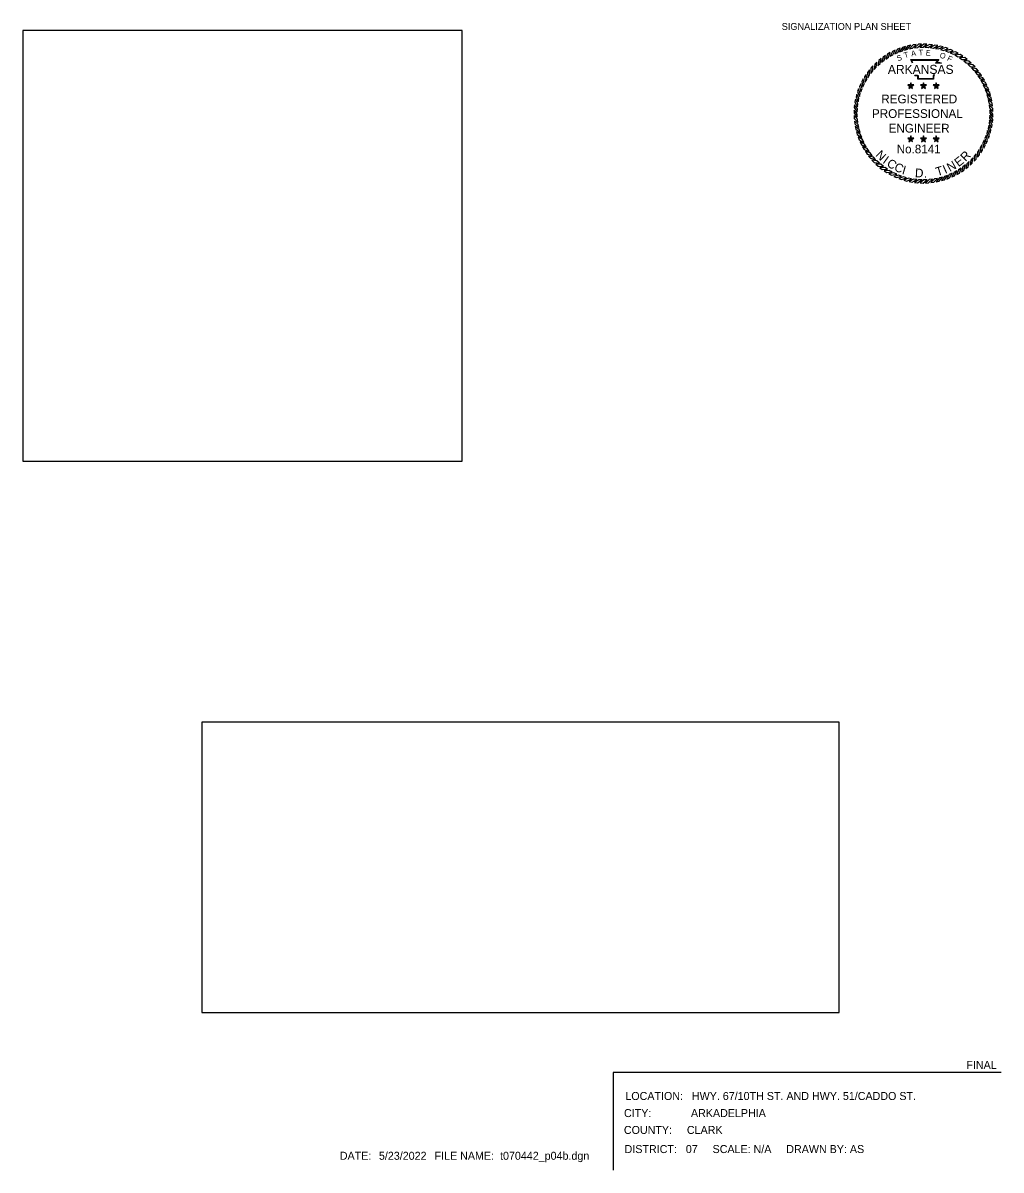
# Model space of a CAD drawing. Extents: x 418532 to 419834, y -565899 to -565283.
# Drawn here: x 419321 to 419834, y -565899 to -565297 of the extents above; entities that cross this region are included whole.
import ezdxf

# ---------------------------------------------------------------- set-up
doc = ezdxf.new("R2010")
doc.units = 0
for name, color, linetype in [('G-ANNO-SYMB', 7, 'Continuous'), ('G-ANNO-TEXT', 7, 'Continuous'), ('Level 10', 7, 'Continuous'), ('Level 57', 7, 'Continuous'), ('V-SIGNAL-LOOP', 7, 'Continuous')]:
    doc.layers.add(name, color=color, linetype=linetype)

msp = doc.modelspace()

# ---------------------------------------------------------------- linework, layer by layer
at = {"layer": 'G-ANNO-SYMB'}
for points in [[(419773.51, -565313.59), (419772.22, -565314.48), (419771.45, -565317.17), (419772.79, -565316.13)], [(419775.97, -565312.12), (419774.61, -565312.9), (419773.63, -565315.52), (419775.05, -565314.59)], [(419778.54, -565310.85), (419777.12, -565311.52), (419775.94, -565314.06), (419777.42, -565313.24)], [(419781.19, -565309.78), (419779.73, -565310.34), (419778.35, -565312.77), (419779.9, -565312.08)], [(419783.93, -565308.93), (419782.42, -565309.37), (419780.86, -565311.69), (419782.45, -565311.11)], [(419786.72, -565308.29), (419785.18, -565308.61), (419783.44, -565310.8), (419785.08, -565310.35)], [(419789.55, -565307.87), (419788, -565308.07), (419786.09, -565310.12), (419787.75, -565309.8)], [(419792.41, -565307.68), (419790.84, -565307.75), (419788.78, -565309.64), (419790.47, -565309.46)], [(419795.27, -565307.71), (419793.71, -565307.66), (419791.5, -565309.38), (419793.2, -565309.33)], [(419798.13, -565307.96), (419796.57, -565307.79), (419794.23, -565309.34), (419795.93, -565309.42)], [(419800.95, -565308.44), (419799.41, -565308.15), (419796.96, -565309.51), (419798.64, -565309.72)], [(419803.73, -565309.14), (419802.21, -565308.73), (419799.67, -565309.89), (419801.33, -565310.23)], [(419806.44, -565310.05), (419804.96, -565309.52), (419802.34, -565310.48), (419803.96, -565310.95)], [(419809.08, -565311.18), (419807.64, -565310.53), (419804.95, -565311.28), (419806.54, -565311.88)], [(419811.61, -565312.5), (419810.24, -565311.75), (419807.49, -565312.29), (419809.03, -565313.01)], [(419814.04, -565314.03), (419812.73, -565313.17), (419809.95, -565313.48), (419811.42, -565314.32)], [(419766.93, -565319.09), (419765.88, -565320.25), (419765.76, -565323.05), (419766.82, -565321.72)], [(419768.98, -565317.09), (419767.84, -565318.16), (419767.5, -565320.94), (419768.66, -565319.7)], [(419771.18, -565315.25), (419769.96, -565316.24), (419769.4, -565318.98), (419770.65, -565317.83)], [(419816.34, -565315.73), (419815.1, -565314.78), (419812.3, -565314.87), (419813.7, -565315.83)], [(419818.5, -565317.62), (419817.33, -565316.56), (419814.54, -565316.44), (419815.86, -565317.5)], [(419820.5, -565319.66), (419819.42, -565318.52), (419816.65, -565318.18), (419817.88, -565319.34)], [(419763.34, -565323.55), (419762.48, -565324.86), (419762.8, -565327.64), (419763.64, -565326.17)], [(419765.05, -565321.25), (419764.09, -565322.49), (419764.19, -565325.29), (419765.14, -565323.88)], [(419822.34, -565321.86), (419821.35, -565320.64), (419818.61, -565320.08), (419819.75, -565321.34)], [(419823.99, -565324.2), (419823.11, -565322.9), (419820.42, -565322.13), (419821.46, -565323.47)], [(419825.46, -565326.65), (419824.68, -565325.29), (419822.06, -565324.31), (419823, -565325.73)], [(419759.37, -565331.15), (419758.84, -565332.62), (419759.8, -565335.25), (419760.27, -565333.62)], [(419760.49, -565328.51), (419759.85, -565329.94), (419760.6, -565332.64), (419761.2, -565331.05)], [(419761.82, -565325.97), (419761.07, -565327.35), (419761.6, -565330.09), (419762.32, -565328.56)], [(419786.78, -565329.61), (419786.41, -565329.1), (419785.2, -565329.1), (419786.18, -565329.81)], [(419786.78, -565329.61), (419786.18, -565329.81), (419785.8, -565330.96), (419786.78, -565330.25)], [(419786.78, -565329.61), (419787.16, -565329.1), (419786.78, -565327.94), (419786.41, -565329.1)], [(419786.78, -565329.61), (419787.39, -565329.81), (419788.37, -565329.1), (419787.16, -565329.1)], [(419786.78, -565329.61), (419786.78, -565330.25), (419787.76, -565330.96), (419787.39, -565329.81)], [(419793.45, -565329.61), (419793.08, -565329.1), (419791.87, -565329.1), (419792.85, -565329.81)], [(419793.45, -565329.61), (419792.85, -565329.81), (419792.47, -565330.96), (419793.45, -565330.25)], [(419793.45, -565329.61), (419793.83, -565329.1), (419793.45, -565327.94), (419793.08, -565329.1)], [(419793.45, -565329.61), (419794.06, -565329.81), (419795.04, -565329.1), (419793.83, -565329.1)], [(419793.45, -565329.61), (419793.45, -565330.25), (419794.43, -565330.96), (419794.06, -565329.81)], [(419800.12, -565329.61), (419799.75, -565329.1), (419798.54, -565329.1), (419799.52, -565329.81)], [(419800.12, -565329.61), (419799.52, -565329.81), (419799.14, -565330.96), (419800.12, -565330.25)], [(419800.12, -565329.61), (419800.5, -565329.1), (419800.12, -565327.94), (419799.75, -565329.1)], [(419800.12, -565329.61), (419800.73, -565329.81), (419801.71, -565329.1), (419800.5, -565329.1)], [(419800.12, -565329.61), (419800.12, -565330.25), (419801.1, -565330.96), (419800.73, -565329.81)], [(419826.74, -565329.22), (419826.07, -565327.8), (419823.53, -565326.62), (419824.35, -565328.11)], [(419827.81, -565331.88), (419827.25, -565330.41), (419824.81, -565329.03), (419825.51, -565330.58)], [(419828.66, -565334.61), (419828.22, -565333.11), (419825.9, -565331.54), (419826.48, -565333.14)], [(419757.76, -565336.64), (419757.47, -565338.18), (419758.82, -565340.62), (419759.03, -565338.94)], [(419758.45, -565333.86), (419758.04, -565335.37), (419759.2, -565337.92), (419759.55, -565336.26)], [(419829.3, -565337.4), (419828.98, -565335.87), (419826.79, -565334.13), (419827.24, -565335.76)], [(419829.72, -565340.24), (419829.52, -565338.68), (419827.47, -565336.77), (419827.79, -565338.44)], [(419757.02, -565342.31), (419756.98, -565343.88), (419758.7, -565346.08), (419758.64, -565344.39)], [(419757.28, -565339.46), (419757.11, -565341.02), (419758.65, -565343.35), (419758.73, -565341.66)], [(419829.91, -565343.09), (419829.83, -565341.53), (419827.94, -565339.47), (419828.13, -565341.15)], [(419829.88, -565345.96), (419829.93, -565344.39), (419828.2, -565342.19), (419828.26, -565343.88)], [(419756.99, -565345.18), (419757.07, -565346.74), (419758.96, -565348.81), (419758.77, -565347.12)], [(419757.19, -565348.04), (419757.39, -565349.59), (419759.43, -565351.5), (419759.11, -565349.83)], [(419829.15, -565351.63), (419829.44, -565350.09), (419828.08, -565347.65), (419827.87, -565349.33)], [(419829.63, -565348.81), (419829.79, -565347.25), (419828.25, -565344.92), (419828.17, -565346.61)], [(419757.6, -565350.87), (419757.93, -565352.4), (419760.11, -565354.14), (419759.67, -565352.51)], [(419758.24, -565353.66), (419758.68, -565355.17), (419761, -565356.73), (419760.43, -565355.13)], [(419826.41, -565359.76), (419827.05, -565358.33), (419826.31, -565355.63), (419825.71, -565357.22)], [(419827.54, -565357.13), (419828.06, -565355.65), (419827.11, -565353.02), (419826.63, -565354.65)], [(419828.45, -565354.41), (419828.86, -565352.9), (419827.7, -565350.35), (419827.36, -565352.01)], [(419759.1, -565356.39), (419759.66, -565357.86), (419762.09, -565359.24), (419761.39, -565357.69)], [(419760.17, -565359.05), (419760.84, -565360.47), (419763.37, -565361.65), (419762.55, -565360.17)], [(419761.44, -565361.62), (419762.22, -565362.98), (419764.84, -565363.96), (419763.91, -565362.54)], [(419786.78, -565357.54), (419786.41, -565357.03), (419785.2, -565357.03), (419786.18, -565357.74)], [(419786.78, -565357.54), (419786.18, -565357.74), (419785.8, -565358.89), (419786.78, -565358.18)], [(419786.78, -565357.54), (419787.16, -565357.03), (419786.78, -565355.87), (419786.41, -565357.03)], [(419786.78, -565357.54), (419787.39, -565357.74), (419788.37, -565357.03), (419787.16, -565357.03)], [(419786.78, -565357.54), (419786.78, -565358.18), (419787.76, -565358.89), (419787.39, -565357.74)], [(419793.45, -565357.54), (419793.08, -565357.03), (419791.87, -565357.03), (419792.85, -565357.74)], [(419793.45, -565357.54), (419792.85, -565357.74), (419792.47, -565358.89), (419793.45, -565358.18)], [(419793.45, -565357.54), (419793.83, -565357.03), (419793.45, -565355.87), (419793.08, -565357.03)], [(419793.45, -565357.54), (419794.06, -565357.74), (419795.04, -565357.03), (419793.83, -565357.03)], [(419793.45, -565357.54), (419793.45, -565358.18), (419794.43, -565358.89), (419794.06, -565357.74)], [(419800.12, -565357.54), (419799.75, -565357.03), (419798.54, -565357.03), (419799.52, -565357.74)], [(419800.12, -565357.54), (419799.52, -565357.74), (419799.14, -565358.89), (419800.12, -565358.18)], [(419800.12, -565357.54), (419800.5, -565357.03), (419800.12, -565355.87), (419799.75, -565357.03)], [(419800.12, -565357.54), (419800.73, -565357.74), (419801.71, -565357.03), (419800.5, -565357.03)], [(419800.12, -565357.54), (419800.12, -565358.18), (419801.1, -565358.89), (419800.73, -565357.74)], [(419823.56, -565364.72), (419824.42, -565363.41), (419824.1, -565360.63), (419823.26, -565362.1)], [(419825.08, -565362.3), (419825.84, -565360.92), (419825.3, -565358.18), (419824.58, -565359.71)], [(419762.91, -565364.07), (419763.79, -565365.37), (419766.48, -565366.14), (419765.44, -565364.8)], [(419764.57, -565366.41), (419765.55, -565367.63), (419768.29, -565368.19), (419767.15, -565366.94)], [(419817.92, -565371.18), (419819.06, -565370.11), (419819.4, -565367.33), (419818.24, -565368.57)], [(419819.97, -565369.18), (419821.02, -565368.02), (419821.14, -565365.22), (419820.09, -565366.55)], [(419821.85, -565367.02), (419822.81, -565365.78), (419822.71, -565362.99), (419821.76, -565364.39)], [(419766.4, -565368.61), (419767.48, -565369.75), (419770.26, -565370.09), (419769.02, -565368.93)], [(419768.41, -565370.65), (419769.57, -565371.71), (419772.36, -565371.83), (419771.04, -565370.77)], [(419770.57, -565372.54), (419771.81, -565373.49), (419774.6, -565373.4), (419773.2, -565372.45)], [(419810.93, -565376.15), (419812.29, -565375.37), (419813.27, -565372.75), (419811.86, -565373.68)], [(419813.39, -565374.68), (419814.69, -565373.79), (419815.46, -565371.11), (419814.12, -565372.14)], [(419815.73, -565373.02), (419816.95, -565372.04), (419817.5, -565369.3), (419816.25, -565370.44)], [(419772.86, -565374.25), (419774.18, -565375.1), (419776.96, -565374.79), (419775.48, -565373.95)], [(419775.29, -565375.77), (419776.67, -565376.52), (419779.41, -565375.99), (419777.88, -565375.26)], [(419777.83, -565377.1), (419779.26, -565377.74), (419781.95, -565376.99), (419780.37, -565376.39)], [(419780.46, -565378.22), (419781.94, -565378.75), (419784.57, -565377.79), (419782.94, -565377.32)], [(419783.18, -565379.13), (419784.69, -565379.54), (419787.23, -565378.38), (419785.57, -565378.04)], [(419785.95, -565379.83), (419787.5, -565380.12), (419789.94, -565378.77), (419788.26, -565378.55)], [(419788.78, -565380.31), (419790.34, -565380.48), (419792.67, -565378.93), (419790.98, -565378.86)], [(419791.63, -565380.57), (419793.2, -565380.61), (419795.4, -565378.89), (419793.71, -565378.94)], [(419794.49, -565380.6), (419796.06, -565380.52), (419798.12, -565378.63), (419796.44, -565378.81)], [(419797.35, -565380.4), (419798.91, -565380.2), (419800.81, -565378.16), (419799.15, -565378.47)], [(419800.18, -565379.98), (419801.72, -565379.66), (419803.46, -565377.47), (419801.83, -565377.92)], [(419802.98, -565379.34), (419804.48, -565378.9), (419806.05, -565376.59), (419804.45, -565377.16)], [(419805.71, -565378.49), (419807.18, -565377.93), (419808.55, -565375.5), (419807.01, -565376.19)], [(419808.37, -565377.42), (419809.78, -565376.75), (419810.97, -565374.22), (419809.48, -565375.03)]]:
    msp.add_lwpolyline(points, close=True, dxfattribs=at)
for points in [[(419787.61, -565317.66), (419786.76, -565315.82), (419801.47, -565315.81), (419800.24, -565317.36), (419801.24, -565317.34), (419802.08, -565317.33), (419802.91, -565317.42)], [(419787.82, -565317.56), (419787.12, -565316.05), (419800.99, -565316.05), (419799.75, -565317.6), (419801.24, -565317.58), (419802.06, -565317.57), (419802.88, -565317.66)], [(419799.15, -565323.83), (419798.9, -565324.03), (419798.82, -565324.34), (419798.73, -565325.1), (419798.73, -565326.12), (419790.52, -565326.12), (419790.52, -565324.74), (419790.52, -565324.44), (419790.19, -565324.34), (419789.02, -565324.34), (419788.81, -565324.02)], [(419799, -565323.65), (419798.7, -565323.9), (419798.59, -565324.29), (419798.5, -565325.09), (419798.5, -565325.88), (419790.75, -565325.88), (419790.75, -565324.74), (419790.75, -565324.27), (419790.22, -565324.1), (419789.15, -565324.1), (419789.01, -565323.89)]]:
    msp.add_lwpolyline(points, dxfattribs=at)
at = {"layer": 'Level 57'}
for points in [[(419630.59, -565847.55), (419630.59, -565898.75)], [(419834.17, -565847.55), (419630.59, -565847.55)]]:
    msp.add_lwpolyline(points, dxfattribs=at)
at = {"layer": 'V-SIGNAL-LOOP'}
for points in [[(419320.6, -565526.59), (419551.15, -565526.59), (419551.15, -565300.56), (419320.6, -565300.56)], [(419414.49, -565816.08), (419749.21, -565816.08), (419749.21, -565663.65), (419414.49, -565663.65)]]:
    msp.add_lwpolyline(points, close=True, dxfattribs=at)

# ---------------------------------------------------------------- texts
at = {"layer": 'G-ANNO-SYMB'}
for s, height, rotation, p in [('S', 2.9, 19.77256, (419779.95, -565316.7)), ('T', 2.9, 16.90148, (419783.64, -565315.04)), ('A', 2.9, 8.67877, (419787.16, -565314.12)), ('T', 2.9, 1.47887, (419790.91, -565313.54)), ('E', 2.9, 356.67203, (419794.62, -565313.63)), ('O', 2.9, 341.2218, (419801.67, -565314.63)), ('F', 2.9, 335.36282, (419805.58, -565316.16)), ('N', 4.59, 315.26758, (419767.97, -565366.13)), ('I', 4.59, 324.21406, (419771.7, -565369.83)), ('E', 4.59, 37.64979, (419811.88, -565372.31)), ('R', 4.59, 45.47796, (419815.54, -565369.54)), ('C', 4.59, 328.68731, (419773.77, -565371.45)), ('C', 4.59, 336.51548, (419777.67, -565373.87)), ('I', 4.59, 344.34365, (419781.87, -565375.74)), ('D', 4.59, 356.64507, (419788.87, -565377.49)), ('T', 4.59, 16.77466, (419800.63, -565377.03)), ('I', 4.59, 24.23006, (419804.84, -565375.82)), ('N', 4.59, 28.7033, (419807.27, -565374.83)), ('.', 4.59, 4.84601, (419793.68, -565377.8))]:
    msp.add_text(s, height=height, rotation=rotation, dxfattribs=at).set_placement(p)
for s, height, p in [('ARKANSAS', 4.737, (419774.73, -565323.3)), ('REGISTERED', 4.585, (419771.29, -565338.76)), ('PROFESSIONAL', 4.5855, (419766.38, -565346.43)), ('ENGINEER', 4.585, (419775.11, -565354.1)), ('No.8141', 4.567, (419779.38, -565365.03))]:
    msp.add_text(s, height=height, dxfattribs=at).set_placement(p)
at = {"layer": 'G-ANNO-TEXT'}
msp.add_text('SIGNALIZATION PLAN SHEET', height=3.6, dxfattribs=at).set_placement((419718.99, -565300.21))
at = {"layer": 'Level 10'}
for s, p in [('FINAL', (419815.96, -565845.65)), ('LOCATION:   HWY. 67/10TH ST. AND HWY. 51/CADDO ST.', (419636.9, -565861.97)), ('CITY:', (419636.19, -565870.93)), (' ARKADELPHIA', (419669.79, -565870.93)), ('COUNTY:     CLARK', (419636.14, -565879.8)), ('DISTRICT:   07     SCALE: N/A     DRAWN BY: AS', (419636.51, -565889.83)), ('DATE:  ', (419486.98, -565893.35)), ('5/23/2022', (419507.52, -565893.35)), ('  FILE NAME: ', (419533.62, -565893.35)), ('t070442_p04b.dgn', (419571.11, -565893.35))]:
    msp.add_text(s, height=4.2, rotation=360, dxfattribs=at).set_placement(p)

doc.saveas('drawing.dxf')
